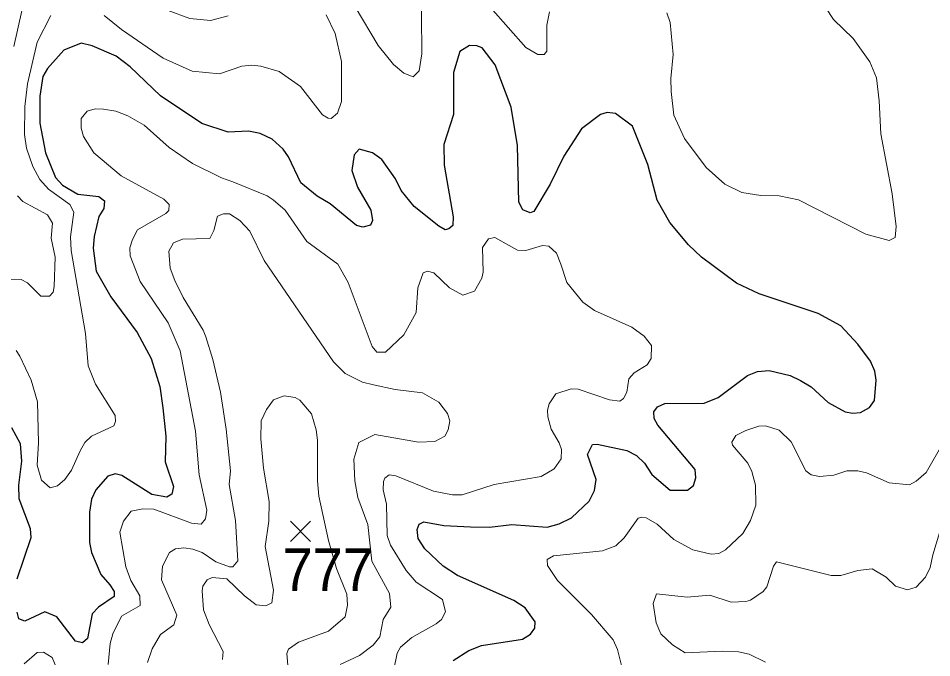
# Model space of a CAD drawing. Extents: x 294.2 to 320.3, y 7482.7 to 7510.7.
# Drawn here: x 303.984 to 305.694, y 7486.646 to 7487.843 of the extents above; entities that cross this region are included whole.
import ezdxf
from ezdxf.enums import TextEntityAlignment as Align

# ---------------------------------------------------------------- set-up
doc = ezdxf.new("R2010")
doc.units = 0
doc.header["$LTSCALE"] = 0.032
for name, color, linetype, lineweight in [('1', 7, 'Continuous', 25), ('2', 7, 'Continuous', 13), ('21', 7, 'Continuous', 25)]:
    doc.layers.add(name, color=color, linetype=linetype, lineweight=lineweight)
doc.layers.add('61', color=7, linetype='Continuous')

msp = doc.modelspace()

# ---------------------------------------------------------------- linework, layer by layer
at = {"layer": '1'}
for points in [[(305.5873, 7487.1823), (305.579, 7487.2005), (305.5554, 7487.2328), (305.5238, 7487.2666), (305.4814, 7487.2897), (305.3708, 7487.3268), (305.3281, 7487.3467), (305.2629, 7487.3951), (305.2385, 7487.4182), (305.2038, 7487.4601), (305.18, 7487.5021), (305.1625, 7487.5688), (305.1334, 7487.6403), (305.1018, 7487.664), (305.0862, 7487.6662), (305.0735, 7487.6624), (305.0383, 7487.6355), (305.005, 7487.5844), (304.9797, 7487.5318), (304.9487, 7487.4807), (304.9423, 7487.4785), (304.9285, 7487.4839), (304.9207, 7487.4984), (304.9185, 7487.6044), (304.9067, 7487.6763), (304.8766, 7487.7555), (304.8524, 7487.7874), (304.8422, 7487.7912), (304.8284, 7487.7918), (304.8106, 7487.7805), (304.7984, 7487.7412), (304.7988, 7487.6626), (304.7803, 7487.606), (304.7809, 7487.5678), (304.7981, 7487.4707), (304.7975, 7487.4547), (304.7898, 7487.4484), (304.7828, 7487.4464), (304.7713, 7487.4534), (304.7252, 7487.49), (304.7008, 7487.5202), (304.6902, 7487.5422), (304.6645, 7487.5779), (304.6467, 7487.5908), (304.6218, 7487.5978), (304.6129, 7487.587), (304.6085, 7487.5574), (304.6188, 7487.5267), (304.6435, 7487.4835), (304.6468, 7487.4641), (304.6434, 7487.4555), (304.629, 7487.4517), (304.6168, 7487.4549), (304.5679, 7487.4952), (304.5435, 7487.5098), (304.513, 7487.5345), (304.4899, 7487.5829), (304.4794, 7487.5974), (304.4588, 7487.6162), (304.4367, 7487.627), (304.415, 7487.6313), (304.377, 7487.6291), (304.3277, 7487.6453), (304.2503, 7487.6973), (304.1935, 7487.7516), (304.1672, 7487.7718), (304.1223, 7487.7912), (304.1018, 7487.7961), (304.0693, 7487.7826), (304.0383, 7487.7487), (304.0299, 7487.7336), (304.0244, 7487.6965), (304.0241, 7487.646), (304.0346, 7487.5905), (304.0535, 7487.5448), (304.0667, 7487.5303), (304.095, 7487.5131), (304.1344, 7487.5088), (304.1455, 7487.5007), (304.1441, 7487.4862), (304.1347, 7487.4717), (304.1258, 7487.434), (304.1241, 7487.4125), (304.1294, 7487.3689), (304.1571, 7487.3213), (304.2061, 7487.2547), (304.2328, 7487.2057), (304.2486, 7487.1535), (304.2542, 7487.1132), (304.26, 7487.0605), (304.2586, 7487.0123), (304.2746, 7486.9663), (304.2714, 7486.9516), (304.2618, 7486.9465), (304.2337, 7486.951)], [(304.7981, 7486.6407), (304.8275, 7486.6592), (304.8511, 7486.6688), (304.9275, 7486.6807), (304.9425, 7486.6899), (304.9508, 7486.7012), (304.9514, 7486.713), (304.9325, 7486.7388), (304.9114, 7486.7528), (304.8058, 7486.7997), (304.779, 7486.8174), (304.7451, 7486.8497), (304.7324, 7486.869), (304.7307, 7486.8857), (304.7343, 7486.8954), (304.7432, 7486.9002), (304.7803, 7486.8932), (304.8305, 7486.8905), (304.866, 7486.89), (304.908, 7486.8948), (304.9737, 7486.8902), (304.9965, 7486.8961), (305.0192, 7486.9074), (305.0528, 7486.9386), (305.0627, 7486.959), (305.0655, 7486.9795), (305.0497, 7487.0263), (305.0585, 7487.0451), (305.0674, 7487.0456), (305.1229, 7487.0338), (305.1412, 7487.0241), (305.1559, 7487.0101), (305.1698, 7486.9886), (305.2041, 7486.9596), (305.2365, 7486.9596), (305.2482, 7486.9682), (305.2521, 7486.9827), (305.251, 7486.9978), (305.1813, 7487.0812), (305.1741, 7487.0935), (305.1736, 7487.1059), (305.1802, 7487.1156), (305.1941, 7487.1215), (305.2678, 7487.122), (305.2942, 7487.1328), (305.3491, 7487.1742), (305.3674, 7487.1817), (305.3893, 7487.1833), (305.4287, 7487.1742), (305.4481, 7487.1645), (305.4683, 7487.1527), (305.5, 7487.1231), (305.5316, 7487.1059)], [(305.5316, 7487.1059), (305.5463, 7487.1032), (305.5607, 7487.1048), (305.5774, 7487.114), (305.5868, 7487.1274), (305.5901, 7487.1651), (305.5873, 7487.1823)], [(303.9819, 7486.7935), (304.0077, 7486.8705), (304.0064, 7486.8871), (303.9853, 7486.9433), (303.9847, 7486.9688), (303.9906, 7487.0135), (303.9879, 7487.0458), (303.9717, 7487.0759)], [(304.2337, 7486.951), (304.1776, 7486.9866), (304.1654, 7486.9898), (304.1515, 7486.9855), (304.129, 7486.9602), (304.1207, 7486.9425), (304.1168, 7486.9183)], [(304.1168, 7486.9183), (304.1168, 7486.8612), (304.1207, 7486.8424), (304.1382, 7486.8015), (304.1554, 7486.7821), (304.1632, 7486.7698), (304.1632, 7486.7606), (304.1338, 7486.7402), (304.1224, 7486.7278), (304.1136, 7486.6817), (304.1042, 7486.6736), (304.0909, 7486.6768), (304.0559, 7486.722), (304.0335, 7486.7317), (303.9963, 7486.714), (303.9847, 7486.7188), (303.9814, 7486.7312)]]:
    msp.add_lwpolyline(points, dxfattribs=at)
at = {"layer": '2'}
for points in [[(304.6142, 7487.864), (304.6576, 7487.7918), (304.6864, 7487.7561), (304.7055, 7487.7395), (304.7228, 7487.7331), (304.7343, 7487.744), (304.7394, 7487.7759), (304.7381, 7487.9215)], [(303.9757, 7487.7899), (303.9987, 7487.8934)], [(305.1978, 7487.8525), (305.2042, 7487.8346), (305.2099, 7487.7746), (305.2054, 7487.7299), (305.2061, 7487.7057), (305.2112, 7487.661), (305.231, 7487.6176), (305.2718, 7487.5632), (305.3063, 7487.532), (305.3383, 7487.5166), (305.3741, 7487.5109), (305.4085, 7487.5102), (305.4443, 7487.5026), (305.5707, 7487.4387), (305.6141, 7487.4266), (305.6256, 7487.4324), (305.6275, 7487.4528), (305.6199, 7487.5141), (305.5987, 7487.6265), (305.5956, 7487.6878), (305.5905, 7487.7312), (305.5783, 7487.7612), (305.5471, 7487.8046), (305.51, 7487.8403), (305.4692, 7487.9023)], [(304.8677, 7487.8627), (304.9341, 7487.788), (304.9565, 7487.7746), (304.9686, 7487.7746), (304.973, 7487.781), (304.973, 7487.8295), (304.9781, 7487.8544)], [(304.0109, 7487.5652), (303.9994, 7487.5997), (303.9956, 7487.6252), (303.9962, 7487.6776), (304.0013, 7487.7197), (304.0192, 7487.7976), (304.0447, 7487.848)], [(304.1443, 7487.8474), (304.1769, 7487.8212), (304.2548, 7487.7676), (304.3091, 7487.7433), (304.3602, 7487.7388), (304.4023, 7487.7529), (304.4202, 7487.7548), (304.438, 7487.7529), (304.4725, 7487.7427), (304.5121, 7487.7146), (304.5536, 7487.6616), (304.5638, 7487.6558), (304.5696, 7487.6552), (304.5817, 7487.6648), (304.5887, 7487.6865), (304.5887, 7487.7018), (304.5887, 7487.7619), (304.5772, 7487.8142), (304.56, 7487.8487)], [(304.2644, 7487.857), (304.3052, 7487.8423), (304.3435, 7487.8384), (304.3768, 7487.8468)], [(304.2656, 7487.4828), (304.2663, 7487.4937), (304.256, 7487.5039), (304.1762, 7487.5479), (304.1251, 7487.5907), (304.106, 7487.6214), (304.1016, 7487.6367), (304.1016, 7487.6552), (304.113, 7487.6686), (304.1277, 7487.6731), (304.1431, 7487.6724), (304.1661, 7487.6686), (304.189, 7487.6597), (304.2197, 7487.6424), (304.2663, 7487.6009), (304.3097, 7487.5709), (304.364, 7487.5441), (304.3857, 7487.5365), (304.4495, 7487.5103), (304.461, 7487.5026), (304.4833, 7487.4834), (304.5242, 7487.4247), (304.5823, 7487.3826), (304.6014, 7487.3481), (304.6461, 7487.2281), (304.6551, 7487.2178), (304.6711, 7487.2178), (304.7055, 7487.2498), (304.7285, 7487.2919), (304.7317, 7487.3379), (304.7419, 7487.366), (304.7496, 7487.3692), (304.7617, 7487.366), (304.7911, 7487.3379), (304.816, 7487.3245), (304.8377, 7487.3315), (304.8517, 7487.3558), (304.8543, 7487.3673), (304.853, 7487.4132), (304.8639, 7487.4298), (304.876, 7487.4324), (304.9182, 7487.4088), (304.9341, 7487.4081), (304.9654, 7487.417), (304.9769, 7487.4158), (304.9916, 7487.403), (304.9993, 7487.3826), (305.0108, 7487.3481), (305.0408, 7487.3111), (305.0625, 7487.2957), (305.1327, 7487.2645), (305.1557, 7487.2478), (305.1691, 7487.23), (305.1684, 7487.2057), (305.1614, 7487.1942), (305.1365, 7487.1789), (305.1269, 7487.168), (305.1231, 7487.1425), (305.1167, 7487.131), (305.1097, 7487.1259), (305.0906, 7487.1284), (305.0318, 7487.1483), (305.0191, 7487.1489), (304.9903, 7487.1399), (304.9775, 7487.1208), (304.9743, 7487.1093), (304.975, 7487.0966), (304.9814, 7487.0736), (304.9967, 7487.048), (305.0005, 7487.0353), (304.9999, 7487.018), (304.9871, 7486.9995), (304.9629, 7486.9848), (304.8748, 7486.9701), (304.8147, 7486.9509), (304.7969, 7486.9509), (304.7611, 7486.9573), (304.6909, 7486.9861), (304.6781, 7486.988), (304.6698, 7486.9816), (304.6678, 7486.9758), (304.6672, 7486.9599), (304.673, 7486.9331), (304.6742, 7486.8744), (304.6806, 7486.8565), (304.71, 7486.8092), (304.7285, 7486.7869), (304.7777, 7486.755), (304.7835, 7486.7314), (304.7764, 7486.7173), (304.7662, 7486.709), (304.7203, 7486.6835), (304.6992, 7486.6656), (304.6928, 7486.6541), (304.687, 7486.6234)], [(304.083, 7487.4081), (304.0817, 7487.4337), (304.0875, 7487.4796), (304.0805, 7487.4937), (304.0403, 7487.5224), (304.0243, 7487.5409), (304.0109, 7487.5652)], [(303.9643, 7487.3545), (303.9892, 7487.3539), (304.0013, 7487.3475), (304.0262, 7487.3225), (304.0422, 7487.3225), (304.0492, 7487.3296), (304.0511, 7487.3405), (304.053, 7487.3954), (304.0454, 7487.4311), (304.0479, 7487.4592), (304.0383, 7487.4745), (303.9924, 7487.4994), (303.9821, 7487.5103)], [(304.212, 7487.35), (304.1935, 7487.3979), (304.1928, 7487.4126), (304.1973, 7487.4286), (304.2069, 7487.4464), (304.2599, 7487.4771), (304.2656, 7487.4828)], [(304.226, 7486.6369), (304.2344, 7486.6624), (304.2503, 7486.6892), (304.2752, 7486.707), (304.2803, 7486.7256), (304.2516, 7486.7914), (304.2535, 7486.8169), (304.2669, 7486.8424), (304.2784, 7486.8495), (304.2937, 7486.8513), (304.3103, 7486.8488), (304.3282, 7486.8424), (304.3538, 7486.8252), (304.3793, 7486.8156), (304.3857, 7486.8156), (304.3946, 7486.8271), (304.3902, 7486.9025), (304.3787, 7486.9701), (304.3812, 7486.9957), (304.3729, 7487.0736), (304.3621, 7487.1425), (304.348, 7487.2038), (304.3346, 7487.246), (304.3301, 7487.2587), (304.2924, 7487.32), (304.2771, 7487.352), (304.2682, 7487.3749), (304.2656, 7487.4069), (304.2745, 7487.4222), (304.2912, 7487.4292), (304.3423, 7487.4305), (304.3499, 7487.4452), (304.357, 7487.472), (304.3678, 7487.4764), (304.3793, 7487.4764), (304.3984, 7487.4643), (304.417, 7487.4439), (304.4444, 7487.389), (304.574, 7487.1993), (304.5957, 7487.1776), (304.6283, 7487.1616), (304.6487, 7487.1565), (304.6896, 7487.1476), (304.7407, 7487.1412), (304.7713, 7487.124), (304.7873, 7487.1029), (304.7917, 7487.0889), (304.7886, 7487.0723), (304.7822, 7487.0601), (304.7637, 7487.0505), (304.733, 7487.0493), (304.6513, 7487.0633), (304.6213, 7487.0487), (304.6117, 7487.0174), (304.6136, 7486.9765), (304.6193, 7486.9459), (304.6379, 7486.8948), (304.6458, 7486.8263), (304.6787, 7486.7658), (304.6813, 7486.7403), (304.6666, 7486.7173), (304.6609, 7486.6847), (304.6481, 7486.6694), (304.6225, 7486.6502), (304.5862, 7486.633)], [(303.9796, 7487.221), (303.9866, 7487.2102), (304.0077, 7487.1655), (304.0198, 7487.1247), (304.0217, 7487.048), (304.0192, 7487.0059), (304.0275, 7486.9778), (304.0434, 7486.9637), (304.0575, 7486.9675), (304.0709, 7486.9791), (304.0837, 7486.997), (304.0996, 7487.0327), (304.1086, 7487.0487), (304.1207, 7487.0602), (304.1628, 7487.0799), (304.166, 7487.0876), (304.1654, 7487.0991), (304.1284, 7487.1579), (304.1149, 7487.1923), (304.1098, 7487.2523), (304.083, 7487.4081)], [(304.152, 7486.633), (304.1558, 7486.6726), (304.1609, 7486.6905), (304.1769, 7486.7237), (304.212, 7486.7435), (304.2114, 7486.7613), (304.1948, 7486.7901), (304.1852, 7486.8156), (304.1737, 7486.8808), (304.1807, 7486.9012), (304.1954, 7486.9203), (304.2171, 7486.9241), (304.2376, 7486.9235), (304.3078, 7486.8973), (304.3263, 7486.896), (304.334, 7486.9056), (304.3365, 7486.9216), (304.3225, 7486.988), (304.3154, 7487.0697), (304.2867, 7487.2204), (304.2643, 7487.2728), (304.212, 7487.35)], [(304.3659, 7486.6426), (304.3672, 7486.6573), (304.3409, 7486.7082), (304.3307, 7486.7352), (304.3282, 7486.7709), (304.3295, 7486.7799), (304.3371, 7486.7913), (304.3467, 7486.7958), (304.3742, 7486.7933), (304.4074, 7486.7613), (304.4291, 7486.7448), (304.447, 7486.7428), (304.4585, 7486.7486), (304.4617, 7486.7722), (304.4457, 7486.8539), (304.4527, 7486.9012), (304.4533, 7486.9382), (304.4431, 7487.0008), (304.438, 7487.0557), (304.4387, 7487.0889), (304.4482, 7487.1106), (304.4617, 7487.1285), (304.4815, 7487.1361), (304.5019, 7487.1329), (304.5108, 7487.1278), (304.5325, 7487.1023), (304.5414, 7487.0723), (304.544, 7487.0531), (304.544, 7486.9765), (304.5465, 7486.9484), (304.5644, 7486.8654), (304.5798, 7486.8129), (304.5989, 7486.7646), (304.6002, 7486.7441), (304.5957, 7486.7224), (304.5645, 7486.6956), (304.5083, 7486.6751), (304.4897, 7486.6617), (304.4865, 7486.6534), (304.4885, 7486.6317)], [(305.118, 7486.6113), (305.1058, 7486.6611), (305.0976, 7486.679), (305.0567, 7486.7268), (304.9935, 7486.79), (304.9743, 7486.8182), (304.9737, 7486.8297), (304.9859, 7486.8367), (305.0778, 7486.8456), (305.1027, 7486.8552), (305.118, 7486.8699), (305.1442, 7486.9069), (305.1512, 7486.9088), (305.1595, 7486.9075), (305.18, 7486.896), (305.2112, 7486.8673), (305.2464, 7486.8475), (305.2808, 7486.8398), (305.2955, 7486.8411), (305.3076, 7486.8475), (305.3402, 7486.8782), (305.3549, 7486.9025), (305.3645, 7486.9312), (305.3638, 7486.9689), (305.3574, 7486.9944), (305.3497, 7487.0097), (305.321, 7487.0435), (305.3198, 7487.0493), (305.3274, 7487.0614), (305.346, 7487.071), (305.3702, 7487.0793), (305.383, 7487.0799), (305.4085, 7487.0717), (305.4309, 7487.0499), (305.4583, 7486.9957), (305.4679, 7486.988), (305.4839, 7486.9848), (305.5107, 7486.9874), (305.5349, 7486.9956), (305.5553, 7486.9956), (305.572, 7486.9918), (305.6141, 7486.9733), (305.6524, 7486.9695)], [(305.6524, 7486.9695), (305.6645, 7486.9759), (305.6837, 7486.9925), (305.7156, 7487.048), (305.7322, 7487.0646), (305.7597, 7487.0768), (305.8503, 7487.0857)], [(305.7501, 7486.9203), (305.7405, 7486.928), (305.7335, 7486.928), (305.7144, 7486.8999), (305.6958, 7486.8386), (305.6907, 7486.8144), (305.6824, 7486.7965)], [(305.6824, 7486.7965), (305.6645, 7486.7779), (305.6486, 7486.7728), (305.6262, 7486.7798), (305.6084, 7486.7965), (305.5822, 7486.8118), (305.5554, 7486.8092), (305.5235, 7486.7997), (305.5056, 7486.7997), (305.4034, 7486.8252), (305.3977, 7486.8169), (305.3849, 7486.7786), (305.3785, 7486.7697), (305.3549, 7486.7537), (305.346, 7486.7511), (305.3185, 7486.7499), (305.2783, 7486.7626), (305.2361, 7486.7588), (305.1787, 7486.7652), (305.1722, 7486.7473), (305.178, 7486.7109), (305.187, 7486.6905), (305.2087, 7486.67), (305.2323, 7486.6547), (305.3013, 7486.6579), (305.3319, 7486.6566), (305.3523, 7486.6521), (305.383, 7486.6375)], [(303.9949, 7486.6343), (304.0192, 7486.6554), (304.0307, 7486.656), (304.0473, 7486.6464), (304.0677, 7486.596)]]:
    msp.add_lwpolyline(points, dxfattribs=at)
at = {"layer": '21'}
for p, q in [((304.4932, 7486.901), (304.5307, 7486.8635)), ((304.5307, 7486.901), (304.4932, 7486.8635))]:
    msp.add_line(p, q, dxfattribs=at)

# ---------------------------------------------------------------- texts
at = {"layer": '61', "width": 0.95}
msp.add_text('777', height=0.08, dxfattribs=at).set_placement((304.5632, 7486.7707), align=Align.CENTER)

doc.saveas('drawing.dxf')
